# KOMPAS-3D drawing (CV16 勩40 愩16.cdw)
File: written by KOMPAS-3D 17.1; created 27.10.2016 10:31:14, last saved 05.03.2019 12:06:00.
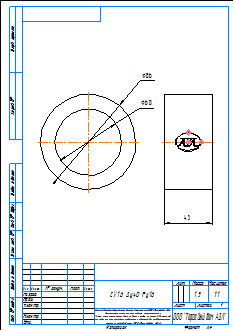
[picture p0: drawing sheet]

Sheet 1: A4, portrait

Title block, sheet 1: name: CV16 Ду40 Ру16; material: Сталь 20  ГОСТ 1050-88; mass: 1,5; sheets: 1; sheet format: A4; stored path: \\adlc.lan\data\АДЛ_ПКД\3D-модели\ADL production\Клапаны обратные ГРАНЛОК\CV16\KOMPAS 2D\CV16 Ду40 Ру16.cdw

Views: Вид 1, Проекционный вид 2
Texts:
  Klimkovich
  ADL
  Рама для чертежей
  Лит-Масса-Масштаб
  Материал-Предприятие
  Масштаб
  Изм.
  Лист
  № докум.
  Подп.
  Дата
  Лит.
  Разраб.
  Пров.
  Т.контр.
  Листов
  Внимание! Данный продукт является объектом авторского права ООО «Торговый Дом АДЛ».
  Запрещается изменение, копирование, распространение
  (в том числе путем копирования на другие сайты и ресурсы в Интернете)
  или любое иное использование информации и объектов без предварительного
  согласия правообладателя (ООО «Торговый Дом АДЛ»).
  Н.контр.
  Утв.
  ООО "Торговый дом АДЛ"
  Изменение
  Номер документа
  Подпись
  Обозначение документа
  Наименование изделия
  Масса изделия по ГОСТ 2.109-73
  Порядковый номер листа
  Общее количество листов в документе
  Характер работы, выполненной лицом, подписавшим документ
  Наименование или индекс предприятия, выпускающего документ
  Инв. № подл.
  Подп. и дата
  Взам. инв. №
  Инв. № дубл.
  Инвентарный номер подлинника по ГОСТ 2.501-68
  Подпись принявшего подлинник в отдел технической документации
  Инвентарный номер подлинника, взамен которого выпущен данный подлинник
  Инвентарный номер дубликата по ГОСТ 2.502-68
  Подпись принявшего дубликат в отдел технической документации
  Справ. №
  Перв. примен.
  Обозначение документа, взамен или на основании которого выпущен данный документ
  Обозначение документа, в котором впервые записан данный документ
  Подпись лица, копировавшего чертеж
  Обозначение формата листа
  !Рама для чертежа
Dimensions and other numbers on the sheet: 86; 60; 43; 1:1; 1; 1,5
